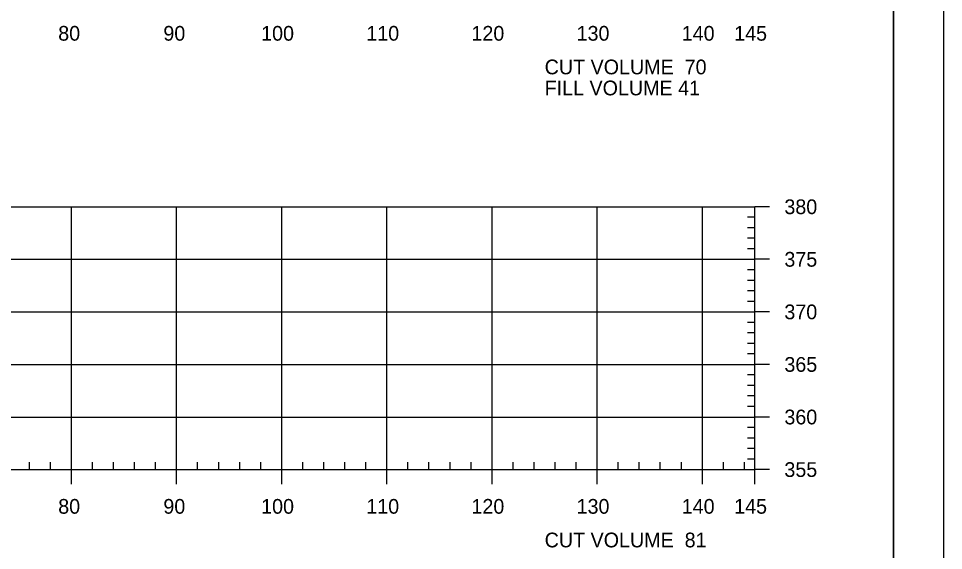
# Model space of a CAD drawing. Extents: x 1359801 to 1362404, y 372415 to 374228.
# Drawn here: x 1360662.5 to 1360750.5, y 372628.5 to 372679.2 of the extents above; entities that cross this region are included whole.
import ezdxf

# ---------------------------------------------------------------- set-up
doc = ezdxf.new("R2010")
doc.units = 0
for name, color, linetype in [('S_MAILBOX', 7, 'Continuous'), ('S_PRIMARY_CTL', 7, 'Continuous'), ('S_SHOULDER', 7, 'Continuous'), ('S_UTL_PT_SYM', 7, 'Continuous'), ('S_WATER_UTILITIES', 7, 'Continuous')]:
    doc.layers.add(name, color=color, linetype=linetype)

msp = doc.modelspace()

# ---------------------------------------------------------------- linework, layer by layer
at = {"layer": 'S_MAILBOX'}
for p, q in [((1360442.53, 372661.246), (1360732.53, 372661.246)), ((1360667.53, 372636.246), (1360667.53, 372661.246)), ((1360677.53, 372636.246), (1360677.53, 372661.246)), ((1360687.53, 372636.246), (1360687.53, 372661.246)), ((1360697.53, 372636.246), (1360697.53, 372661.246)), ((1360707.53, 372636.246), (1360707.53, 372661.246)), ((1360717.53, 372636.246), (1360717.53, 372661.246)), ((1360727.53, 372636.246), (1360727.53, 372661.246)), ((1360732.53, 372636.246), (1360732.53, 372661.246)), ((1360442.53, 372656.246), (1360732.53, 372656.246)), ((1360442.53, 372651.246), (1360732.53, 372651.246)), ((1360442.53, 372646.246), (1360732.53, 372646.246)), ((1360442.53, 372641.246), (1360732.53, 372641.246)), ((1360442.53, 372636.246), (1360732.53, 372636.246))]:
    msp.add_line(p, q, dxfattribs=at)
at = {"layer": 'S_SHOULDER'}
for points in [[(1360417.123, 372734.6), (1360750.463, 372734.6), (1360750.463, 372521.263), (1360417.123, 372521.263)], [(1360663.45, 372730.706), (1360663.45, 372720.826), (1360699.182, 372720.826), (1360699.182, 372717.906), (1360722.382, 372717.906), (1360722.382, 372693.573), (1360745.71, 372693.573), (1360745.71, 372525.246), (1360429.53, 372525.246), (1360429.53, 372730.706)]]:
    msp.add_lwpolyline(points, close=True, dxfattribs=at)
at = {"layer": 'S_UTL_PT_SYM'}
msp.add_line((1360745.71, 372525.246), (1360745.71, 372730.706), dxfattribs=at)
at = {"layer": 'S_WATER_UTILITIES'}
for p, q in [((1360732.53, 372636.246), (1360732.53, 372661.246)), ((1360733.93, 372661.246), (1360732.53, 372661.246)), ((1360732.53, 372660.246), (1360731.83, 372660.246)), ((1360732.53, 372659.246), (1360731.83, 372659.246)), ((1360732.53, 372658.246), (1360731.83, 372658.246)), ((1360732.53, 372657.246), (1360731.83, 372657.246)), ((1360733.93, 372656.246), (1360732.53, 372656.246)), ((1360732.53, 372655.246), (1360731.83, 372655.246)), ((1360732.53, 372654.246), (1360731.83, 372654.246)), ((1360732.53, 372653.246), (1360731.83, 372653.246)), ((1360732.53, 372652.246), (1360731.83, 372652.246)), ((1360733.93, 372651.246), (1360732.53, 372651.246)), ((1360732.53, 372650.246), (1360731.83, 372650.246)), ((1360732.53, 372649.246), (1360731.83, 372649.246)), ((1360732.53, 372648.246), (1360731.83, 372648.246)), ((1360732.53, 372647.246), (1360731.83, 372647.246)), ((1360733.93, 372646.246), (1360732.53, 372646.246)), ((1360732.53, 372645.246), (1360731.83, 372645.246)), ((1360732.53, 372644.246), (1360731.83, 372644.246)), ((1360732.53, 372643.246), (1360731.83, 372643.246)), ((1360732.53, 372642.246), (1360731.83, 372642.246)), ((1360733.93, 372641.246), (1360732.53, 372641.246)), ((1360732.53, 372640.246), (1360731.83, 372640.246)), ((1360732.53, 372639.246), (1360731.83, 372639.246)), ((1360732.53, 372638.246), (1360731.83, 372638.246)), ((1360663.53, 372636.246), (1360663.53, 372636.946)), ((1360665.53, 372636.246), (1360665.53, 372636.946)), ((1360669.53, 372636.246), (1360669.53, 372636.946)), ((1360671.53, 372636.246), (1360671.53, 372636.946)), ((1360673.53, 372636.246), (1360673.53, 372636.946)), ((1360675.53, 372636.246), (1360675.53, 372636.946)), ((1360679.53, 372636.246), (1360679.53, 372636.946)), ((1360681.53, 372636.246), (1360681.53, 372636.946)), ((1360683.53, 372636.246), (1360683.53, 372636.946)), ((1360685.53, 372636.246), (1360685.53, 372636.946)), ((1360689.53, 372636.246), (1360689.53, 372636.946)), ((1360691.53, 372636.246), (1360691.53, 372636.946)), ((1360693.53, 372636.246), (1360693.53, 372636.946)), ((1360695.53, 372636.246), (1360695.53, 372636.946)), ((1360699.53, 372636.246), (1360699.53, 372636.946)), ((1360701.53, 372636.246), (1360701.53, 372636.946)), ((1360703.53, 372636.246), (1360703.53, 372636.946)), ((1360705.53, 372636.246), (1360705.53, 372636.946)), ((1360709.53, 372636.246), (1360709.53, 372636.946)), ((1360711.53, 372636.246), (1360711.53, 372636.946)), ((1360713.53, 372636.246), (1360713.53, 372636.946)), ((1360715.53, 372636.246), (1360715.53, 372636.946)), ((1360719.53, 372636.246), (1360719.53, 372636.946)), ((1360721.53, 372636.246), (1360721.53, 372636.946)), ((1360723.53, 372636.246), (1360723.53, 372636.946)), ((1360725.53, 372636.246), (1360725.53, 372636.946)), ((1360729.53, 372636.246), (1360729.53, 372636.946)), ((1360731.53, 372636.246), (1360731.53, 372636.946)), ((1360732.53, 372637.246), (1360731.83, 372637.246)), ((1360442.53, 372636.246), (1360732.53, 372636.246)), ((1360667.53, 372634.846), (1360667.53, 372636.246)), ((1360677.53, 372634.846), (1360677.53, 372636.246)), ((1360687.53, 372634.846), (1360687.53, 372636.246)), ((1360697.53, 372634.846), (1360697.53, 372636.246)), ((1360707.53, 372634.846), (1360707.53, 372636.246)), ((1360717.53, 372634.846), (1360717.53, 372636.246)), ((1360727.53, 372634.846), (1360727.53, 372636.246)), ((1360732.53, 372634.846), (1360732.53, 372636.246)), ((1360733.93, 372636.246), (1360732.53, 372636.246))]:
    msp.add_line(p, q, dxfattribs=at)

# ---------------------------------------------------------------- texts
at = {"layer": 'S_PRIMARY_CTL'}
for s, p in [('80', (1360666.269, 372677.046)), ('90', (1360676.269, 372677.046)), ('100', (1360685.569, 372677.046)), ('110', (1360695.569, 372677.046)), ('120', (1360705.569, 372677.046)), ('130', (1360715.569, 372677.046)), ('140', (1360725.569, 372677.046)), ('145', (1360730.556, 372677.046)), ('CUT VOLUME  70', (1360712.53, 372673.846)), ('FILL VOLUME 41', (1360712.53, 372671.846)), ('380', (1360735.33, 372660.546)), ('375', (1360735.33, 372655.546)), ('370', (1360735.33, 372650.546)), ('365', (1360735.33, 372645.546)), ('360', (1360735.33, 372640.546)), ('355', (1360735.33, 372635.546)), ('80', (1360666.269, 372632.046)), ('90', (1360676.269, 372632.046)), ('100', (1360685.569, 372632.046)), ('110', (1360695.569, 372632.046)), ('120', (1360705.569, 372632.046)), ('130', (1360715.569, 372632.046)), ('140', (1360725.569, 372632.046)), ('145', (1360730.556, 372632.046)), ('CUT VOLUME  81', (1360712.53, 372628.846))]:
    msp.add_text(s, height=1.4, dxfattribs=at).set_placement(p)

doc.saveas('drawing.dxf')
